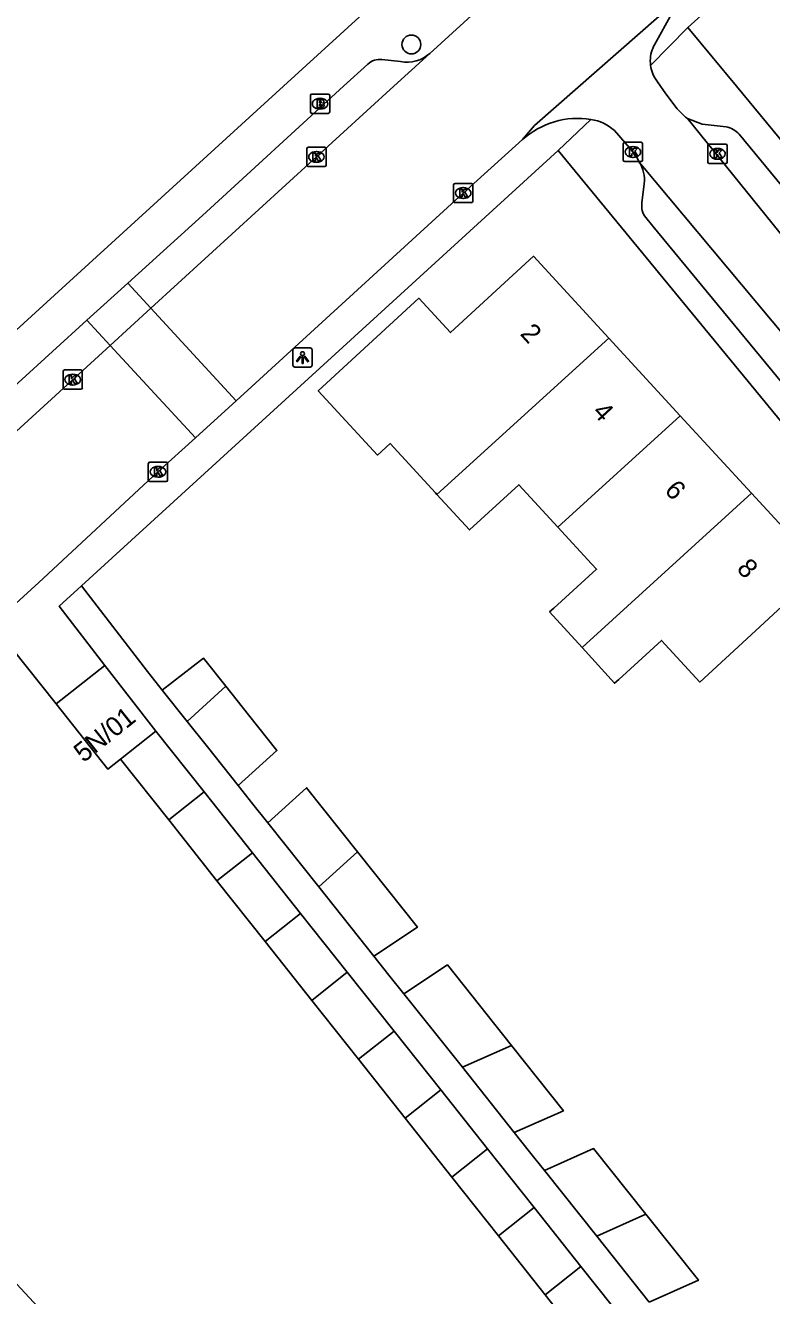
# Model space of a CAD drawing. Extents: x 163150 to 163546, y 380933 to 381635.
# Drawn here: x 163213 to 163251.7, y 381187.2 to 381253.2 of the extents above; entities that cross this region are included whole.
import ezdxf

# ---------------------------------------------------------------- set-up
doc = ezdxf.new("R2010")
doc.units = 0
for name, color, linetype in [('IMGEO_Boom', 7, 'Continuous'), ('IMGEO_Brandkraan', 7, 'Continuous'), ('IMGEO_Kolk', 7, 'Continuous'), ('IMGEO_Lichtpunt', 7, 'Continuous'), ('IMGEO_Pand', 7, 'Continuous'), ('IMGEO_Pand_nummerreeks', 7, 'Continuous'), ('IMGEO_Parkeervlak_open', 7, 'Continuous'), ('IMGEO_Rijbaan_lokaal_open', 7, 'Continuous'), ('IMGEO_Voetpad_open', 7, 'Continuous')]:
    doc.layers.add(name, color=color, linetype=linetype)

msp = doc.modelspace()

# ---------------------------------------------------------------- linework, layer by layer
at = {"layer": 'IMGEO_Boom'}
msp.add_circle((163233.012, 381252.17), 0.489, dxfattribs=at)
at = {"layer": 'IMGEO_Brandkraan'}
for p, q in [((163227.847, 381249.595), (163228.699, 381249.595)), ((163227.772, 381248.669), (163227.772, 381249.521)), ((163228.26, 381249.375), (163228.285, 381249.375)), ((163228.773, 381249.521), (163228.773, 381248.669)), ((163228.699, 381248.595), (163227.847, 381248.595)), ((163228.283, 381248.815), (163228.258, 381248.815))]:
    msp.add_line(p, q, dxfattribs=at)
for points in [[(163227.847, 381249.595), (163228.699, 381249.595)], [(163227.772, 381248.669), (163227.772, 381249.521)], [(163228.12, 381249.295), (163228.12, 381248.895), (163228.333, 381248.895)], [(163228.351, 381249.295), (163228.12, 381249.295)], [(163228.299, 381249.214), (163228.245, 381249.214), (163228.245, 381249.138)], [(163228.245, 381249.138), (163228.298, 381249.138)], [(163228.307, 381249.062), (163228.245, 381249.062), (163228.245, 381248.981)], [(163228.245, 381248.981), (163228.307, 381248.981)], [(163228.773, 381249.521), (163228.773, 381248.669)], [(163228.699, 381248.595), (163227.847, 381248.595)]]:
    msp.add_lwpolyline(points, dxfattribs=at)
for centre, radius, start, end in [((163227.849, 381249.519), 0.0765, 91.55205, 178.44795), ((163227.849, 381249.519), 0.0765, 91.55205, 178.44795), ((163228.697, 381249.519), 0.0765, 1.55205, 88.44795), ((163228.697, 381249.519), 0.0765, 1.55205, 88.44795), ((163228.3, 381249.176), 0.0379, 267.82845, 90.93552), ((163228.308, 381249.021), 0.0404, 269.87594, 90.50774), ((163228.339, 381249.146), 0.251, 268.66757, 293.53466), ((163228.355, 381249.15), 0.145, 59.4692, 91.53667), ((163228.38, 381249.197), 0.0922, 285.51372, 58.15012), ((163228.385, 381249.005), 0.105, 301.31148, 78.98903), ((163227.849, 381248.671), 0.0765, 181.55205, 268.44795), ((163227.849, 381248.671), 0.0765, 181.55205, 268.44795), ((163228.697, 381248.671), 0.0765, 271.55205, 358.44795), ((163228.697, 381248.671), 0.0765, 271.55205, 358.44795)]:
    msp.add_arc(centre, radius, start, end, dxfattribs=at)
for centre, major_axis, ratio, start_param, end_param in [((163228.259, 381249.095), (-0.387, 0.002), 0.722429, 4.712389, 7.853982), ((163228.284, 381249.095), (-0.39, 0.002), 0.717154, 1.570796, 4.712389)]:
    msp.add_ellipse(centre, major_axis=major_axis, ratio=ratio, start_param=start_param, end_param=end_param, dxfattribs=at)
at = {"layer": 'IMGEO_Kolk'}
for p, q in [((163244.014, 381246.165), (163244.014, 381247.017)), ((163244.089, 381247.091), (163244.941, 381247.091)), ((163245.015, 381247.017), (163245.015, 381246.165)), ((163248.406, 381246.068), (163248.406, 381246.92)), ((163248.481, 381246.994), (163249.333, 381246.994)), ((163249.407, 381246.92), (163249.407, 381246.068)), ((163227.585, 381245.909), (163227.585, 381246.761)), ((163227.66, 381246.835), (163228.512, 381246.835)), ((163228.073, 381246.615), (163228.098, 381246.615)), ((163228.586, 381246.761), (163228.586, 381245.909)), ((163244.525, 381246.311), (163244.5, 381246.311)), ((163244.502, 381246.871), (163244.527, 381246.871)), ((163248.894, 381246.774), (163248.919, 381246.774)), ((163228.512, 381245.835), (163227.66, 381245.835)), ((163228.096, 381246.055), (163228.071, 381246.055)), ((163244.941, 381246.091), (163244.089, 381246.091)), ((163249.333, 381245.994), (163248.481, 381245.994)), ((163248.917, 381246.214), (163248.892, 381246.214)), ((163235.279, 381244.959), (163236.131, 381244.959)), ((163235.204, 381244.033), (163235.204, 381244.885)), ((163235.692, 381244.739), (163235.717, 381244.739)), ((163236.205, 381244.885), (163236.205, 381244.033)), ((163236.131, 381243.959), (163235.279, 381243.959)), ((163235.715, 381244.179), (163235.69, 381244.179)), ((163214.93, 381234.349), (163214.93, 381235.201)), ((163215.005, 381235.275), (163215.857, 381235.275)), ((163215.418, 381235.055), (163215.443, 381235.055)), ((163215.931, 381235.201), (163215.931, 381234.349)), ((163215.441, 381234.495), (163215.416, 381234.495)), ((163215.857, 381234.275), (163215.005, 381234.275)), ((163219.432, 381230.49), (163220.284, 381230.49)), ((163219.357, 381229.564), (163219.357, 381230.416)), ((163219.845, 381230.27), (163219.87, 381230.27)), ((163220.358, 381230.416), (163220.358, 381229.564)), ((163220.284, 381229.49), (163219.432, 381229.49)), ((163219.868, 381229.71), (163219.843, 381229.71))]:
    msp.add_line(p, q, dxfattribs=at)
for points in [[(163244.014, 381246.165), (163244.014, 381247.017)], [(163244.089, 381247.091), (163244.941, 381247.091)], [(163245.015, 381247.017), (163245.015, 381246.165)], [(163248.406, 381246.068), (163248.406, 381246.92)], [(163248.481, 381246.994), (163249.333, 381246.994)], [(163249.407, 381246.92), (163249.407, 381246.068)], [(163227.585, 381245.909), (163227.585, 381246.761)], [(163227.66, 381246.835), (163228.512, 381246.835)], [(163227.906, 381246.535), (163228.029, 381246.535), (163228.029, 381246.384), (163228.159, 381246.535), (163228.323, 381246.535), (163228.177, 381246.384), (163228.33, 381246.135), (163228.178, 381246.135), (163228.093, 381246.299), (163228.029, 381246.232), (163228.029, 381246.135), (163227.906, 381246.135), (163227.906, 381246.535)], [(163228.586, 381246.761), (163228.586, 381245.909)], [(163244.335, 381246.791), (163244.458, 381246.791), (163244.458, 381246.64), (163244.588, 381246.791), (163244.752, 381246.791), (163244.606, 381246.64), (163244.759, 381246.391), (163244.607, 381246.391), (163244.522, 381246.555), (163244.458, 381246.488), (163244.458, 381246.391), (163244.335, 381246.391), (163244.335, 381246.791)], [(163248.727, 381246.694), (163248.85, 381246.694), (163248.85, 381246.543), (163248.98, 381246.694), (163249.144, 381246.694), (163248.998, 381246.543), (163249.151, 381246.294), (163248.999, 381246.294), (163248.914, 381246.458), (163248.85, 381246.391), (163248.85, 381246.294), (163248.727, 381246.294), (163248.727, 381246.694)], [(163228.512, 381245.835), (163227.66, 381245.835)], [(163244.941, 381246.091), (163244.089, 381246.091)], [(163249.333, 381245.994), (163248.481, 381245.994)], [(163235.279, 381244.959), (163236.131, 381244.959)], [(163235.204, 381244.033), (163235.204, 381244.885)], [(163235.525, 381244.659), (163235.648, 381244.659), (163235.648, 381244.508), (163235.778, 381244.659), (163235.942, 381244.659), (163235.796, 381244.508), (163235.949, 381244.259), (163235.797, 381244.259), (163235.712, 381244.423), (163235.648, 381244.356), (163235.648, 381244.259), (163235.525, 381244.259), (163235.525, 381244.659)], [(163236.205, 381244.885), (163236.205, 381244.033)], [(163236.131, 381243.959), (163235.279, 381243.959)], [(163214.93, 381234.349), (163214.93, 381235.201)], [(163215.005, 381235.275), (163215.857, 381235.275)], [(163215.931, 381235.201), (163215.931, 381234.349)], [(163215.251, 381234.975), (163215.374, 381234.975), (163215.374, 381234.824), (163215.504, 381234.975), (163215.668, 381234.975), (163215.522, 381234.824), (163215.675, 381234.575), (163215.523, 381234.575), (163215.438, 381234.739), (163215.374, 381234.672), (163215.374, 381234.575), (163215.251, 381234.575), (163215.251, 381234.975)], [(163215.857, 381234.275), (163215.005, 381234.275)], [(163219.432, 381230.49), (163220.284, 381230.49)], [(163219.357, 381229.564), (163219.357, 381230.416)], [(163219.678, 381230.19), (163219.801, 381230.19), (163219.801, 381230.039), (163219.931, 381230.19), (163220.095, 381230.19), (163219.949, 381230.039), (163220.102, 381229.79), (163219.95, 381229.79), (163219.865, 381229.954), (163219.801, 381229.887), (163219.801, 381229.79), (163219.678, 381229.79), (163219.678, 381230.19)], [(163220.358, 381230.416), (163220.358, 381229.564)], [(163220.284, 381229.49), (163219.432, 381229.49)]]:
    msp.add_lwpolyline(points, dxfattribs=at)
for centre, start, end in [((163244.091, 381247.015), 91.55205, 178.44795), ((163244.091, 381247.015), 91.55205, 178.44795), ((163244.939, 381247.015), 1.55205, 88.44795), ((163244.939, 381247.015), 1.55205, 88.44795), ((163248.483, 381246.918), 91.55205, 178.44795), ((163248.483, 381246.918), 91.55205, 178.44795), ((163249.331, 381246.918), 1.55205, 88.44795), ((163249.331, 381246.918), 1.55205, 88.44795), ((163227.662, 381246.759), 91.55205, 178.44795), ((163227.662, 381246.759), 91.55205, 178.44795), ((163228.51, 381246.759), 1.55205, 88.44795), ((163228.51, 381246.759), 1.55205, 88.44795), ((163227.662, 381245.911), 181.55205, 268.44795), ((163227.662, 381245.911), 181.55205, 268.44795), ((163228.51, 381245.911), 271.55205, 358.44795), ((163228.51, 381245.911), 271.55205, 358.44795), ((163244.091, 381246.167), 181.55205, 268.44795), ((163244.091, 381246.167), 181.55205, 268.44795), ((163244.939, 381246.167), 271.55205, 358.44795), ((163244.939, 381246.167), 271.55205, 358.44795), ((163248.483, 381246.07), 181.55205, 268.44795), ((163248.483, 381246.07), 181.55205, 268.44795), ((163249.331, 381246.07), 271.55205, 358.44795), ((163249.331, 381246.07), 271.55205, 358.44795), ((163235.281, 381244.883), 91.55205, 178.44795), ((163235.281, 381244.883), 91.55205, 178.44795), ((163236.129, 381244.883), 1.55205, 88.44795), ((163236.129, 381244.883), 1.55205, 88.44795), ((163235.281, 381244.035), 181.55205, 268.44795), ((163235.281, 381244.035), 181.55205, 268.44795), ((163236.129, 381244.035), 271.55205, 358.44795), ((163236.129, 381244.035), 271.55205, 358.44795), ((163215.007, 381235.199), 91.55205, 178.44795), ((163215.007, 381235.199), 91.55205, 178.44795), ((163215.855, 381235.199), 1.55205, 88.44795), ((163215.855, 381235.199), 1.55205, 88.44795), ((163215.007, 381234.351), 181.55205, 268.44795), ((163215.007, 381234.351), 181.55205, 268.44795), ((163215.855, 381234.351), 271.55205, 358.44795), ((163215.855, 381234.351), 271.55205, 358.44795), ((163219.434, 381230.414), 91.55205, 178.44795), ((163219.434, 381230.414), 91.55205, 178.44795), ((163220.282, 381230.414), 1.55205, 88.44795), ((163220.282, 381230.414), 1.55205, 88.44795), ((163219.434, 381229.566), 181.55205, 268.44795), ((163219.434, 381229.566), 181.55205, 268.44795), ((163220.282, 381229.566), 271.55205, 358.44795), ((163220.282, 381229.566), 271.55205, 358.44795)]:
    msp.add_arc(centre, 0.0765, start, end, dxfattribs=at)
for centre, major_axis, ratio, start_param, end_param in [((163228.072, 381246.335), (-0.387, 0.002), 0.722429, 4.712389, 7.853982), ((163228.097, 381246.335), (-0.39, 0.002), 0.717154, 1.570796, 4.712389), ((163244.501, 381246.591), (-0.387, 0.002), 0.722429, 4.712389, 7.853982), ((163244.526, 381246.591), (-0.39, 0.002), 0.717154, 1.570796, 4.712389), ((163248.893, 381246.494), (-0.387, 0.002), 0.722429, 4.712389, 7.853982), ((163248.918, 381246.494), (-0.39, 0.002), 0.717154, 1.570796, 4.712389), ((163235.691, 381244.459), (-0.387, 0.002), 0.722429, 4.712389, 7.853982), ((163235.716, 381244.459), (-0.39, 0.002), 0.717154, 1.570796, 4.712389), ((163215.417, 381234.775), (-0.387, 0.002), 0.722429, 4.712389, 7.853982), ((163215.442, 381234.775), (-0.39, 0.002), 0.717154, 1.570796, 4.712389), ((163219.844, 381229.99), (-0.387, 0.002), 0.722429, 4.712389, 7.853982), ((163219.869, 381229.99), (-0.39, 0.002), 0.717154, 1.570796, 4.712389)]:
    msp.add_ellipse(centre, major_axis=major_axis, ratio=ratio, start_param=start_param, end_param=end_param, dxfattribs=at)
at = {"layer": 'IMGEO_Lichtpunt'}
for p, q in [((163227.766, 381236.419), (163226.958, 381236.419)), ((163227.766, 381236.419), (163226.958, 381236.419)), ((163226.864, 381236.324), (163226.864, 381235.517)), ((163226.864, 381236.324), (163226.864, 381235.517)), ((163227.86, 381235.517), (163227.86, 381236.324)), ((163227.86, 381235.517), (163227.86, 381236.324)), ((163226.958, 381235.423), (163227.766, 381235.423)), ((163226.958, 381235.423), (163227.766, 381235.423))]:
    msp.add_line(p, q, dxfattribs=at)
for points in [[(163227.238, 381235.988), (163227.277, 381235.96), (163227.089, 381235.698), (163227.051, 381235.725), (163227.238, 381235.988)], [(163227.34, 381235.94), (163227.387, 381235.94), (163227.387, 381235.618), (163227.34, 381235.618), (163227.34, 381235.94)], [(163227.45, 381235.96), (163227.488, 381235.987), (163227.675, 381235.725), (163227.636, 381235.697), (163227.45, 381235.96)]]:
    msp.add_lwpolyline(points, dxfattribs=at)
msp.add_circle((163227.363, 381236.122), 0.0994, dxfattribs=at)
for centre, start, end in [((163226.958, 381236.324), 90, 180), ((163226.958, 381236.324), 90, 180), ((163227.766, 381236.324), 0, 90), ((163227.766, 381236.324), 0, 90), ((163226.958, 381235.517), 180, 270), ((163226.958, 381235.517), 180, 270), ((163227.766, 381235.517), 270, 0), ((163227.766, 381235.517), 270, 360)]:
    msp.add_arc(centre, 0.0946, start, end, dxfattribs=at)
at = {"layer": 'IMGEO_Pand'}
for points in [[(163234.331, 381228.815), (163234.257, 381228.896), (163231.904, 381231.451), (163231.255, 381230.854), (163228.181, 381234.192), (163233.402, 381239), (163235.045, 381237.216), (163239.346, 381241.177), (163243.256, 381236.931)], [(163243.256, 381236.931), (163234.331, 381228.815)], [(163243.256, 381236.931), (163246.967, 381232.901)], [(163240.613, 381227.123), (163246.967, 381232.901)], [(163246.967, 381232.901), (163250.677, 381228.873)], [(163240.613, 381227.123), (163238.595, 381229.314), (163236.025, 381226.976), (163234.331, 381228.815)], [(163250.677, 381228.873), (163254.325, 381224.911), (163250.648, 381221.524), (163247.986, 381219.073), (163245.994, 381221.236), (163243.775, 381219.218), (163243.555, 381219.018), (163241.872, 381220.867)], [(163250.677, 381228.873), (163242.092, 381221.067), (163241.872, 381220.867)], [(163241.872, 381220.867), (163240.189, 381222.716), (163240.409, 381222.916), (163242.629, 381224.934), (163242.371, 381225.214), (163240.613, 381227.123)], [(163214.572, 381217.942), (163217.096, 381219.943)], [(163219.753, 381216.521), (163217.096, 381219.943)], [(163220.084, 381218.649), (163222.224, 381220.31), (163223.381, 381218.857)], [(163220.084, 381218.649), (163221.372, 381217.031)], [(163221.372, 381217.031), (163223.381, 381218.857)], [(163223.381, 381218.857), (163224.562, 381217.373), (163226.03, 381215.529), (163224.021, 381213.703)], [(163214.572, 381217.942), (163217.257, 381214.555), (163217.919, 381215.076)], [(163221.372, 381217.031), (163222.422, 381215.712), (163224.021, 381213.703)], [(163217.919, 381215.076), (163219.753, 381216.521)], [(163222.251, 381213.377), (163219.753, 381216.521)], [(163217.919, 381215.076), (163220.418, 381211.924)], [(163220.418, 381211.924), (163222.251, 381213.377)], [(163224.757, 381210.221), (163222.251, 381213.377)], [(163225.563, 381211.766), (163227.571, 381213.592), (163230.216, 381210.268)], [(163220.418, 381211.924), (163222.921, 381208.766)], [(163225.563, 381211.766), (163228.208, 381208.443)], [(163224.757, 381210.221), (163222.921, 381208.766)], [(163227.263, 381207.066), (163224.757, 381210.221)], [(163228.208, 381208.443), (163230.216, 381210.268)], [(163230.216, 381210.268), (163233.329, 381206.356), (163231.071, 381204.847)], [(163222.921, 381208.766), (163225.424, 381205.608)], [(163228.208, 381208.443), (163231.071, 381204.847)], [(163225.424, 381205.608), (163227.263, 381207.066)], [(163229.688, 381204.014), (163227.263, 381207.066)], [(163225.424, 381205.608), (163227.846, 381202.554)], [(163232.628, 381202.89), (163234.887, 381204.399), (163238.211, 381200.222)], [(163229.688, 381204.014), (163227.846, 381202.554)], [(163232.112, 381200.962), (163229.688, 381204.014)], [(163232.628, 381202.89), (163235.659, 381199.082)], [(163227.846, 381202.554), (163230.267, 381199.5)], [(163230.267, 381199.5), (163232.112, 381200.962)], [(163234.536, 381197.91), (163232.112, 381200.962)], [(163235.659, 381199.082), (163238.211, 381200.222)], [(163238.211, 381200.222), (163240.909, 381196.832), (163238.357, 381195.692)], [(163230.267, 381199.5), (163232.688, 381196.445)], [(163235.659, 381199.082), (163238.357, 381195.692)], [(163234.536, 381197.91), (163232.688, 381196.445)], [(163236.963, 381194.855), (163234.536, 381197.91)], [(163232.688, 381196.445), (163235.112, 381193.388)], [(163235.112, 381193.388), (163236.963, 381194.855)], [(163239.39, 381191.8), (163236.963, 381194.855)], [(163239.922, 381193.727), (163242.472, 381194.867), (163245.185, 381191.458)], [(163239.922, 381193.727), (163242.635, 381190.319)], [(163235.112, 381193.388), (163237.536, 381190.33)], [(163237.536, 381190.33), (163239.39, 381191.8)], [(163239.39, 381191.8), (163241.817, 381188.745)], [(163217.586, 381182.386), (163209.644, 381190.918)], [(163242.635, 381190.319), (163245.185, 381191.458)], [(163245.185, 381191.458), (163247.913, 381188.03), (163245.363, 381186.892)], [(163237.536, 381190.33), (163239.96, 381187.273)], [(163242.635, 381190.319), (163245.363, 381186.892)], [(163241.817, 381188.745), (163239.96, 381187.273)], [(163244.247, 381185.685), (163241.817, 381188.745)], [(163239.96, 381187.273), (163242.387, 381184.211)]]:
    msp.add_lwpolyline(points, dxfattribs=at)
at = {"layer": 'IMGEO_Parkeervlak_open'}
for points in [[(163218.285, 381239.782), (163219.487, 381238.478)], [(163217.374, 381236.548), (163216.162, 381237.86)]]:
    msp.add_lwpolyline(points, dxfattribs=at)
at = {"layer": 'IMGEO_Rijbaan_lokaal_open'}
for points in [[(163243.582, 381260.479), (163233.963, 381251.702)], [(163247.004, 381254.649), (163239.4, 381247.963), (163238.786, 381247.234)], [(163247.004, 381254.649), (163245.557, 381252)], [(163233.963, 381251.702), (163232.1, 381250), (163219.487, 381238.478)], [(163245.791, 381250.237), (163246.226, 381249.615), (163246.806, 381248.824), (163247.241, 381248.394), (163247.344, 381248.323)], [(163254.133, 381239.93), (163247.344, 381248.323)], [(163244.845, 381246.068), (163244.673, 381246.416), (163243.559, 381247.709)], [(163238.786, 381247.234), (163235.706, 381244.458), (163223.919, 381233.668)], [(163244.845, 381246.068), (163257.059, 381231.46)], [(163219.487, 381238.478), (163217.374, 381236.548)], [(163219.487, 381238.478), (163223.919, 381233.668)], [(163217.374, 381236.548), (163198.3, 381219.123)], [(163221.799, 381231.758), (163217.374, 381236.548)], [(163223.919, 381233.668), (163221.799, 381231.758)], [(163188.892, 381201.601), (163190.329, 381202.954), (163213.677, 381224.249), (163219.855, 381229.989), (163221.799, 381231.758)]]:
    msp.add_lwpolyline(points, dxfattribs=at)
for centre, radius, start, end in [((163247.146, 381251.315), 1.73, 156.68383, 187.61803), ((163247.16, 381251.318), 1.744, 187.65146, 218.30517), ((163241.664, 381244.027), 4.309, 81.02378, 131.9003), ((163241.925, 381245.817), 2.5, 49.18407, 80.53106)]:
    msp.add_arc(centre, radius, start, end, dxfattribs=at)
at = {"layer": 'IMGEO_Voetpad_open'}
for points in [[(163198.814, 381224.874), (163226.368, 381250), (163269.177, 381289.036), (163267.999, 381290.328), (163270.661, 381292.68)], [(163286.554, 381278.836), (163284.028, 381278.488), (163275.144, 381277.265), (163274.301, 381277.041), (163273.554, 381276.589), (163260.303, 381264.494), (163260.154, 381264.566), (163247.371, 381253.054)], [(163245.431, 381251.086), (163247.371, 381253.054)], [(163247.371, 381253.054), (163249.895, 381250), (163266.785, 381229.563), (163266.853, 381229.481)], [(163230.753, 381251.154), (163229.487, 381250), (163222.173, 381243.296), (163218.285, 381239.782)], [(163232.451, 381251.288), (163231.488, 381251.393)], [(163240.64, 381246.663), (163242.336, 381248.283)], [(163247.344, 381248.323), (163248.102, 381248.033), (163249.349, 381247.9)], [(163250.029, 381247.52), (163253.614, 381243.176)], [(163240.64, 381246.663), (163215.881, 381224.069)], [(163282.659, 381139.767), (163292.918, 381150.971), (163261.531, 381220.959), (163260.513, 381222.504), (163240.64, 381246.663)], [(163244.982, 381243.949), (163245.106, 381244.944)], [(163262.732, 381221.585), (163260.84, 381224.198), (163255.077, 381231.183), (163245.546, 381242.743), (163245.181, 381243.186)], [(163218.285, 381239.782), (163216.162, 381237.86)], [(163216.162, 381237.86), (163212.606, 381234.604), (163211.236, 381233.36), (163199.094, 381222.29)], [(163217.096, 381219.943), (163214.736, 381223.024), (163215.881, 381224.069)], [(163215.881, 381224.069), (163219.309, 381219.623), (163220.084, 381218.649)], [(163190.07, 381200.655), (163212.265, 381220.831), (163214.572, 381217.942)], [(163224.021, 381213.703), (163224.791, 381212.736), (163225.563, 381211.766)], [(163231.071, 381204.847), (163231.85, 381203.868), (163232.628, 381202.89)], [(163238.357, 381195.692), (163239.147, 381194.7), (163239.922, 381193.727)]]:
    msp.add_lwpolyline(points, dxfattribs=at)
for centre, radius, start, end in [((163232.797, 381252.993), 1.74, 258.53826, 312.08738), ((163231.391, 381250.442), 0.956, 84.17009, 131.85586), ((163249.057, 381246.58), 1.352, 44.06248, 77.54255), ((163243.276, 381245.111), 1.838, 354.77757, 31.36797), ((163245.969, 381243.799), 0.999, 171.36142, 217.87422)]:
    msp.add_arc(centre, radius, start, end, dxfattribs=at)

# ---------------------------------------------------------------- texts
at = {"layer": 'IMGEO_Pand_nummerreeks'}
for s, rotation, p in [('2', 312.64129, (163238.618, 381237.125)), ('4', 312.64129, (163242.364, 381233.058)), ('6', 312.63931, (163246.109, 381228.992)), ('8', 312.63931, (163249.856, 381224.923)), ('5N/01', 38.54694, (163215.993, 381214.866))]:
    msp.add_text(s, height=1, rotation=rotation, dxfattribs=at).set_placement(p)

doc.saveas('drawing.dxf')
